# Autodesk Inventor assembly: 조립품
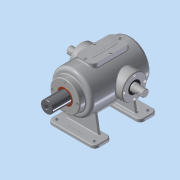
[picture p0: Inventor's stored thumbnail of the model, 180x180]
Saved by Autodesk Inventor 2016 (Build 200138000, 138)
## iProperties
Created: 2018-11
Part Number: 조립품
Material: 일반
Document SubType Name: Assembly
Designer: 공506_43
Mass: 8191.27 g
Surface Area: 4241.81 cm^2
Volume: 1855.49 cm^3
Density: 4.41462 g/cm^3
Author: 공506_43
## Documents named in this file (15)
- C:\Users\공506_43\Desktop\381121V1009\조립품.iam
- C:\Users\공506_43\Desktop\381121V1009\가변스프링.ipt
- C:\Users\공506_43\Desktop\381121V1009\베어링 6205.ipt
- 베어링 6205.ipt
- C:\Users\공506_43\Desktop\381121V1009\본체.ipt
- C:\Users\공506_43\Desktop\381121V1009\볼트 M4x0.7.ipt
- C:\Users\공506_43\Desktop\381121V1009\부시.ipt
- C:\Users\공506_43\Desktop\381121V1009\상부커버.ipt
- C:\Users\공506_43\Desktop\381121V1009\슬라이드 커버.ipt
- C:\Users\공506_43\Desktop\381121V1009\슬라이드.ipt
- C:\Users\공506_43\Desktop\381121V1009\오일실.ipt
- 오일실.ipt
- C:\Users\공506_43\Desktop\381121V1009\육각머리볼트 M4.ipt
- C:\Users\공506_43\Desktop\381121V1009\축 커버.ipt
- C:\Users\공506_43\Desktop\381121V1009\편심축.ipt
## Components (13 placed, 2 different names)
1. 가변스프링:1
2. M4x0.7:3
3. M4x0.7:4
4. M4x0.7:5
5. M4x0.7:6
6. M4x0.7:1
7. M4x0.7:7
8. M4x0.7:8
9. M4x0.7:9
10. M4x0.7:2
11. M4x0.7:10
12. M4x0.7:11
13. M4x0.7:12
